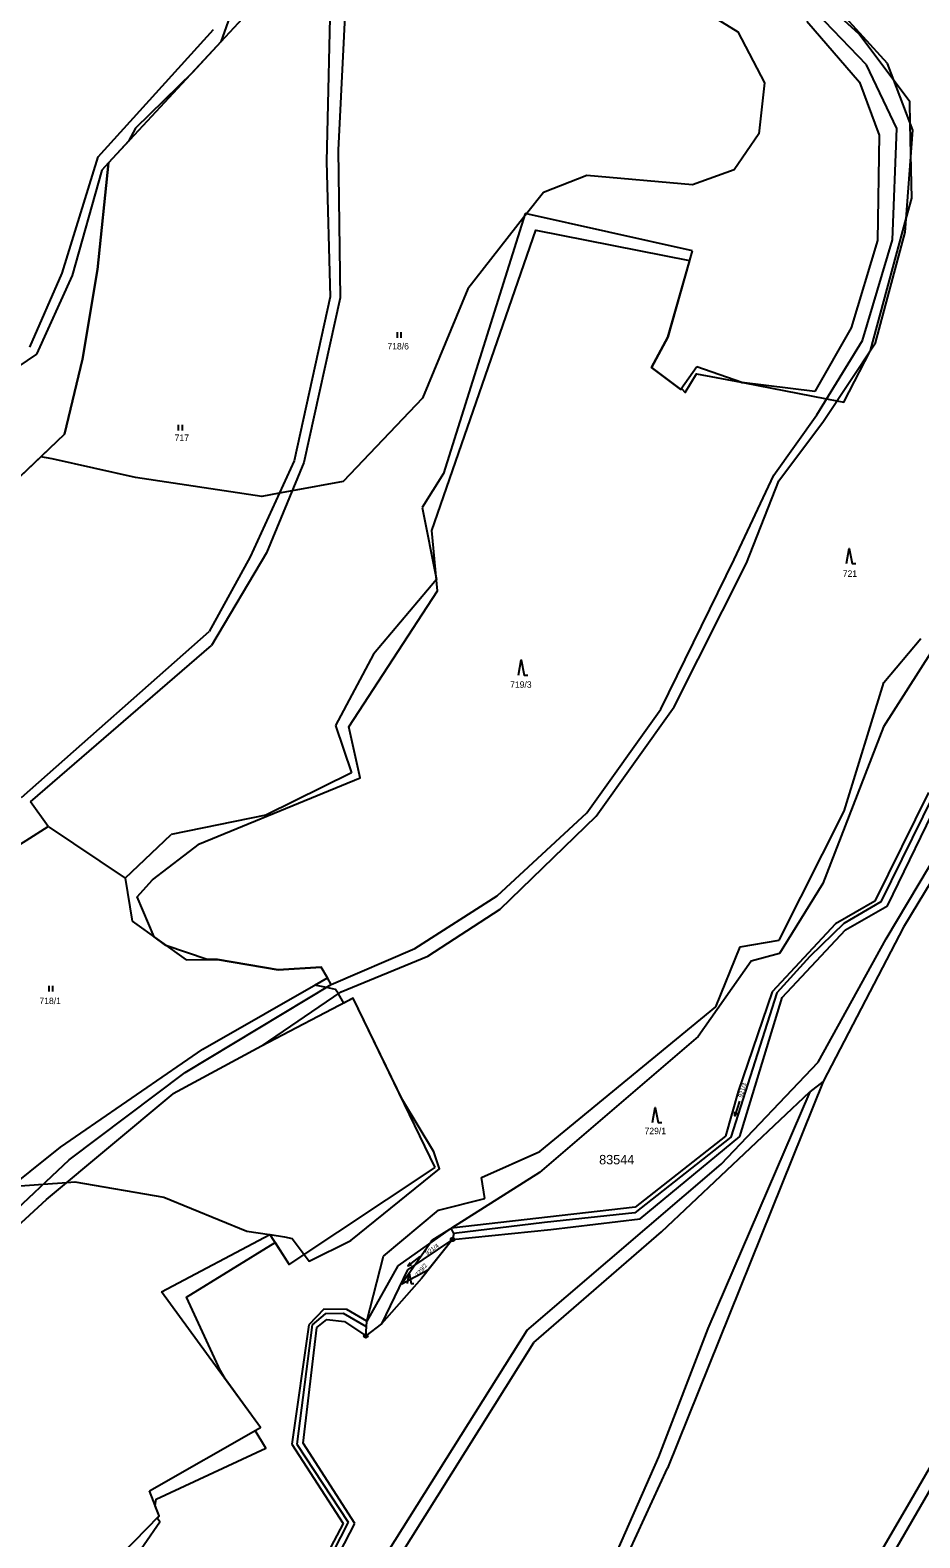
# Model space of a CAD drawing. Extents: x -547623 to -538651, y -1096714 to -1086522.
# Drawn here: x -544362.8 to -544127.4, y -1093972.7 to -1093573.6 of the extents above; entities that cross this region are included whole.
import ezdxf

# ---------------------------------------------------------------- set-up
doc = ezdxf.new("R2010")
doc.units = 0
for name, color, linetype in [('Vrstva 1', 7, 'Continuous'), ('Vrstva 25', 7, 'Continuous'), ('Vrstva 41', 7, 'Continuous'), ('Vrstva 52', 7, 'Continuous'), ('Vrstva 53', 7, 'Continuous'), ('Vrstva 83', 7, 'Continuous'), ('Vrstva 86', 7, 'Continuous')]:
    doc.layers.add(name, color=color, linetype=linetype)

msp = doc.modelspace()

# ---------------------------------------------------------------- linework, layer by layer
at = {"layer": 'Vrstva 1'}
for points in [[(-544141.5, -1093582.7), (-544165.76, -1093557.36)], [(-544283.31, -1093558.84), (-544284.44, -1093608.36)], [(-544279.15, -1093560.88), (-544281.34, -1093605.3)], [(-544342.12, -1093608.69), (-544305.41, -1093569.13)], [(-544135.89, -1093582.35), (-544148.81, -1093568.22)], [(-544344.88, -1093607.09), (-544314.3, -1093573.38)], [(-544157.24, -1093571.16), (-544143.3, -1093587.3)], [(-544129.25, -1093600.01), (-544135.89, -1093582.35)], [(-544133.47, -1093599.59), (-544141.5, -1093582.7)], [(-544143.3, -1093587.3), (-544138.16, -1093601.33)], [(-544138.16, -1093601.33), (-544138.53, -1093629.26)], [(-544134.56, -1093629.07), (-544133.47, -1093599.59)], [(-544131.24, -1093627.07), (-544129.25, -1093600.01)], [(-544281.34, -1093605.3), (-544280.82, -1093644.45)], [(-544354.36, -1093637.91), (-544344.88, -1093607.09)], [(-544345.05, -1093636.88), (-544342.12, -1093608.69)], [(-544342.12, -1093608.69), (-544343.89, -1093610.63)], [(-544284.44, -1093608.36), (-544283.42, -1093644.15)], [(-544343.89, -1093610.63), (-544351.69, -1093638.52)], [(-544231.86, -1093622.13), (-544253.47, -1093690.89)], [(-544187.58, -1093631.95), (-544231.86, -1093622.13)], [(-544138.53, -1093629.26), (-544145.5, -1093652.33)], [(-544142.53, -1093655.71), (-544134.56, -1093629.07)], [(-544139.11, -1093656.3), (-544131.24, -1093627.07)], [(-544194.09, -1093654.8), (-544187.58, -1093631.95)], [(-544362.97, -1093657.45), (-544354.36, -1093637.91)], [(-544351.69, -1093638.52), (-544361.15, -1093659.37)], [(-544349.04, -1093660.69), (-544345.05, -1093636.88)], [(-544283.42, -1093644.15), (-544292.98, -1093687.56)], [(-544280.82, -1093644.45), (-544290.41, -1093688.03)], [(-544145.5, -1093652.33), (-544155.19, -1093669.26)], [(-544198.37, -1093662.83), (-544194.09, -1093654.8)], [(-544154.63, -1093675.36), (-544142.53, -1093655.71)], [(-544152.89, -1093677.05), (-544139.11, -1093656.3)], [(-544361.15, -1093659.37), (-544377.72, -1093670.57)], [(-544353.73, -1093680.49), (-544349.04, -1093660.69)], [(-544190.67, -1093668.66), (-544198.37, -1093662.83)], [(-544186.41, -1093662.65), (-544190.67, -1093668.66)], [(-544174.49, -1093666.83), (-544186.41, -1093662.65)], [(-544155.19, -1093669.26), (-544174.49, -1093666.83)], [(-544166.02, -1093691.38), (-544154.63, -1093675.36)], [(-544164.71, -1093692.89), (-544152.89, -1093677.05)], [(-544373.17, -1093698.99), (-544353.73, -1093680.49)], [(-544292.98, -1093687.56), (-544304.58, -1093712.95)], [(-544290.41, -1093688.03), (-544300.33, -1093711.96)], [(-544253.47, -1093690.89), (-544259.1, -1093699.96)], [(-544176.52, -1093713.7), (-544166.02, -1093691.38)], [(-544173.22, -1093714.7), (-544164.71, -1093692.89)], [(-544259.1, -1093699.96), (-544255.29, -1093719.03)], [(-544304.58, -1093712.95), (-544315.47, -1093732.72)], [(-544300.33, -1093711.96), (-544314.83, -1093736.49)], [(-544195.95, -1093753.28), (-544176.52, -1093713.7)], [(-544192.41, -1093752.68), (-544173.22, -1093714.7)], [(-544255.29, -1093719.03), (-544271.97, -1093738.72)], [(-544365.17, -1093776.69), (-544315.47, -1093732.72)], [(-544362.73, -1093777.86), (-544314.83, -1093736.49)], [(-544136.87, -1093746.24), (-544127.14, -1093734.57)], [(-544271.97, -1093738.72), (-544282.06, -1093757.6)], [(-544147.37, -1093780.34), (-544136.87, -1093746.24)], [(-544215.48, -1093780.72), (-544195.95, -1093753.28)], [(-544213.06, -1093781.67), (-544192.41, -1093752.68)], [(-544096.01, -1093752.19), (-544131.68, -1093811.05)], [(-544282.06, -1093757.6), (-544277.77, -1093770.15)], [(-544277.77, -1093770.15), (-544300.51, -1093781.38)], [(-544358.11, -1093784.34), (-544362.73, -1093777.86)], [(-544125.06, -1093775.35), (-544139.27, -1093804.11)], [(-544135.92, -1093805.37), (-544121.21, -1093775.05)], [(-544300.51, -1093781.38), (-544325.53, -1093786.51)], [(-544239.28, -1093802.74), (-544215.48, -1093780.72)], [(-544238.42, -1093806.24), (-544213.06, -1093781.67)], [(-544164.59, -1093814.46), (-544147.37, -1093780.34)], [(-544136.31, -1093814.14), (-544116.37, -1093780.69)], [(-544397.19, -1093809.18), (-544358.11, -1093784.34)], [(-544358.11, -1093784.34), (-544337.71, -1093798.08)], [(-544337.71, -1093798.08), (-544325.53, -1093786.51)], [(-544337.71, -1093798.08), (-544335.89, -1093809.47)], [(-544261, -1093816.64), (-544239.28, -1093802.74)], [(-544139.27, -1093804.11), (-544149.67, -1093810.15)], [(-544147.08, -1093811.76), (-544135.92, -1093805.37)], [(-544335.89, -1093809.47), (-544321.59, -1093819.68)], [(-544257.58, -1093818.7), (-544238.42, -1093806.24)], [(-544149.67, -1093810.15), (-544166.48, -1093828.17)], [(-544163.84, -1093829.61), (-544147.08, -1093811.76)], [(-544154.25, -1093846.76), (-544136.31, -1093814.14)], [(-544131.68, -1093811.05), (-544152.92, -1093851.86)], [(-544283.19, -1093826.23), (-544261, -1093816.64)], [(-544181.34, -1093832.12), (-544174.95, -1093816.27)], [(-544174.95, -1093816.27), (-544164.59, -1093814.46)], [(-544321.59, -1093819.68), (-544313.28, -1093819.6)], [(-544313.28, -1093819.6), (-544297.25, -1093822.37)], [(-544297.25, -1093822.37), (-544285.85, -1093821.61)], [(-544284.19, -1093824.46), (-544285.85, -1093821.61)], [(-544280.55, -1093828.19), (-544257.58, -1093818.7)], [(-544317.12, -1093843.32), (-544284.19, -1093824.46)], [(-544283.19, -1093826.23), (-544284.19, -1093824.46)], [(-544321.81, -1093849.54), (-544283.19, -1093826.23)], [(-544301.62, -1093842.5), (-544280.55, -1093828.19)], [(-544277.34, -1093829.83), (-544301.62, -1093842.5)], [(-544255.62, -1093874.7), (-544277.34, -1093829.83)], [(-544166.48, -1093828.17), (-544175.45, -1093854.57)], [(-544175, -1093866.49), (-544163.84, -1093829.61)], [(-544227.91, -1093870.45), (-544181.34, -1093832.12)], [(-544354.81, -1093869.25), (-544317.12, -1093843.32)], [(-544301.62, -1093842.5), (-544325.04, -1093855.17)], [(-544352.52, -1093872.65), (-544321.81, -1093849.54)], [(-544179.98, -1093873.82), (-544154.25, -1093846.76)], [(-544152.92, -1093851.86), (-544194.16, -1093954.3)], [(-544152.92, -1093851.86), (-544156.46, -1093854.59)], [(-544358.53, -1093883.13), (-544325.04, -1093855.17)], [(-544195.78, -1093891.69), (-544156.46, -1093854.59)], [(-544156.46, -1093854.59), (-544183.51, -1093917.25)], [(-544175.45, -1093854.57), (-544178.77, -1093866.4)], [(-544387.06, -1093895.07), (-544354.81, -1093869.25)], [(-544178.77, -1093866.4), (-544202.71, -1093885.17)], [(-544201.42, -1093888.29), (-544175, -1093866.49)], [(-544403.16, -1093920.26), (-544352.52, -1093872.65)], [(-544243.42, -1093877.28), (-544227.91, -1093870.45)], [(-544199.51, -1093890.51), (-544179.98, -1093873.82)], [(-544294.33, -1093900.31), (-544255.62, -1093874.7)], [(-544242.53, -1093882.86), (-544243.42, -1093877.28)], [(-544400.78, -1093921.99), (-544358.53, -1093883.13)], [(-544269.29, -1093898.12), (-544254.78, -1093885.96)], [(-544254.78, -1093885.96), (-544242.53, -1093882.86)], [(-544202.71, -1093885.17), (-544251.38, -1093890.73)], [(-544225.05, -1093891.11), (-544201.42, -1093888.29)], [(-544328.06, -1093907.6), (-544299.39, -1093892.36)], [(-544299.39, -1093892.36), (-544294.33, -1093900.31)], [(-544251.38, -1093890.73), (-544265.53, -1093900.71)], [(-544251.02, -1093893.7), (-544263, -1093901.78)], [(-544250.68, -1093892.15), (-544251.38, -1093890.73)], [(-544251.02, -1093893.7), (-544225.05, -1093891.11)], [(-544231.42, -1093917.78), (-544199.51, -1093890.51)], [(-544229.5, -1093920.98), (-544195.78, -1093891.69)], [(-544273.74, -1093915.31), (-544269.29, -1093898.12)], [(-544265.53, -1093900.71), (-544273.74, -1093915.31)], [(-544263, -1093901.78), (-544269.87, -1093916.09)], [(-544301.89, -1093943.46), (-544328.06, -1093907.6)], [(-544285.1, -1093912.17), (-544289.1, -1093916.33)], [(-544279.03, -1093912.25), (-544285.1, -1093912.17)], [(-544273.74, -1093915.31), (-544279.03, -1093912.25)], [(-544289.1, -1093916.33), (-544293.56, -1093947.89)], [(-544290.56, -1093947.68), (-544286.96, -1093917)], [(-544286.96, -1093917), (-544284.33, -1093914.88)], [(-544284.33, -1093914.88), (-544279.68, -1093915.4)], [(-544279.68, -1093915.4), (-544274.01, -1093919.25)], [(-544273.83, -1093916.82), (-544273.74, -1093915.31)], [(-544231.42, -1093917.78), (-544268.23, -1093976.49)], [(-544183.51, -1093917.25), (-544196.54, -1093951.3)], [(-544265.71, -1093978.73), (-544229.5, -1093920.98)], [(-544102, -1093920.7), (-544141.53, -1093989.17)], [(-544331.28, -1093960.3), (-544301.89, -1093943.46)], [(-544293.56, -1093947.89), (-544280.03, -1093968.88)], [(-544276.92, -1093968.88), (-544290.56, -1093947.68)], [(-544196.54, -1093951.3), (-544221.1, -1094006.97)], [(-544218.52, -1094007.2), (-544194.16, -1093954.3)], [(-544328.67, -1093966.87), (-544331.28, -1093960.3)], [(-544355.24, -1093994.15), (-544328.67, -1093966.87)], [(-544280.03, -1093968.88), (-544285.81, -1093979.92)], [(-544283.7, -1093982.03), (-544276.92, -1093968.88)]]:
    msp.add_lwpolyline(points, dxfattribs=at)
at = {"layer": 'Vrstva 25'}
for p, q in [((-544265.62, -1093655.01), (-544265.62, -1093653.51)), ((-544264.62, -1093655.01), (-544264.62, -1093653.51)), ((-544323.55, -1093679.51), (-544323.55, -1093678.01)), ((-544322.55, -1093679.51), (-544322.55, -1093678.01)), ((-544357.86, -1093828.08), (-544357.86, -1093826.58)), ((-544356.86, -1093828.08), (-544356.86, -1093826.58))]:
    msp.add_line(p, q, dxfattribs=at)
for points in [[(-544146.81, -1093714.77), (-544146.11, -1093710.77), (-544145.31, -1093714.77), (-544144.31, -1093714.77)], [(-544233.58, -1093744.28), (-544232.88, -1093740.28), (-544232.08, -1093744.28), (-544231.08, -1093744.28)], [(-544175.11, -1093857.14), (-544176.33, -1093860.98), (-544175.7, -1093860.12)], [(-544198.13, -1093862.76), (-544197.43, -1093858.76), (-544196.63, -1093862.76), (-544195.63, -1093862.76)], [(-544176.33, -1093860.98), (-544176.34, -1093859.92)], [(-544259.71, -1093898.26), (-544262.91, -1093900.7), (-544261.91, -1093900.35)], [(-544262.91, -1093900.7), (-544262.31, -1093899.82)], [(-544262.99, -1093905.34), (-544262.52, -1093902.66), (-544261.98, -1093905.34), (-544261.31, -1093905.34)]]:
    msp.add_lwpolyline(points, dxfattribs=at)
at = {"layer": 'Vrstva 41'}
for points in [[(-544123.85, -1093776.18), (-544137.68, -1093804.35)], [(-544123.85, -1093776.18), (-544137.68, -1093804.35)], [(-544137.68, -1093804.35), (-544147.48, -1093810.02)], [(-544137.68, -1093804.35), (-544147.48, -1093810.02)], [(-544147.48, -1093810.02), (-544156.45, -1093818.84)], [(-544147.48, -1093810.02), (-544156.45, -1093818.84)], [(-544156.45, -1093818.84), (-544165.26, -1093828.42)], [(-544156.45, -1093818.84), (-544165.26, -1093828.42)], [(-544165.26, -1093828.42), (-544177.36, -1093866.67)], [(-544165.26, -1093828.42), (-544177.36, -1093866.67)], [(-544177.36, -1093866.67), (-544202.78, -1093886.65)], [(-544177.36, -1093866.67), (-544202.78, -1093886.65)], [(-544226.67, -1093889.25), (-544250.68, -1093892.15)], [(-544226.67, -1093889.25), (-544250.68, -1093892.15)], [(-544202.78, -1093886.65), (-544226.67, -1093889.25)], [(-544202.78, -1093886.65), (-544226.67, -1093889.25)], [(-544251.02, -1093893.7), (-544259.26, -1093904.01)], [(-544251.02, -1093893.7), (-544259.26, -1093904.01)], [(-544250.68, -1093892.15), (-544251.02, -1093893.7)], [(-544250.68, -1093892.15), (-544251.02, -1093893.7)], [(-544259.26, -1093904.01), (-544269.87, -1093916.09)], [(-544259.26, -1093904.01), (-544269.87, -1093916.09)], [(-544098.58, -1093908.92), (-544129.74, -1093962.73)], [(-544098.58, -1093908.92), (-544129.74, -1093962.73)], [(-544284.77, -1093913.36), (-544288.2, -1093916.31)], [(-544284.77, -1093913.36), (-544288.2, -1093916.31)], [(-544279.95, -1093913.28), (-544284.77, -1093913.36)], [(-544279.95, -1093913.28), (-544284.77, -1093913.36)], [(-544273.83, -1093916.82), (-544279.95, -1093913.28)], [(-544273.83, -1093916.82), (-544279.95, -1093913.28)], [(-544288.2, -1093916.31), (-544292.28, -1093947.9)], [(-544288.2, -1093916.31), (-544292.28, -1093947.9)], [(-544269.87, -1093916.09), (-544274.01, -1093919.25)], [(-544269.87, -1093916.09), (-544274.01, -1093919.25)], [(-544274.01, -1093919.25), (-544273.83, -1093916.82)], [(-544274.01, -1093919.25), (-544273.83, -1093916.82)], [(-544292.28, -1093947.9), (-544278.65, -1093968.55)], [(-544292.28, -1093947.9), (-544278.65, -1093968.55)], [(-544129.74, -1093962.73), (-544145.32, -1093989.4)], [(-544129.74, -1093962.73), (-544145.32, -1093989.4)], [(-544278.65, -1093968.55), (-544284.88, -1093980.64)], [(-544278.65, -1093968.55), (-544284.88, -1093980.64)]]:
    msp.add_lwpolyline(points, dxfattribs=at)
at = {"layer": 'Vrstva 52'}
for points in [[(-544315.02, -1093518.45), (-544313.07, -1093532.25), (-544312.07, -1093533.51), (-544309.06, -1093537.66), (-544307.5, -1093545.43), (-544307.5, -1093563.41), (-544309.52, -1093568.66), (-544312.37, -1093576.64), (-544319.88, -1093584.73), (-544335, -1093599.5), (-544336.81, -1093602.97), (-544342.12, -1093608.69), (-544345.05, -1093636.88), (-544349.04, -1093660.69), (-544353.73, -1093680.49), (-544360.06, -1093686.51)], [(-544290.36, -1093897.68), (-544289, -1093899.5), (-544278, -1093894), (-544254.5, -1093875), (-544256, -1093870.5), (-544264.29, -1093856.79), (-544277.34, -1093829.83), (-544279.81, -1093831.12), (-544281.28, -1093828.69), (-544282, -1093827.5), (-544284.44, -1093826.99), (-544287.48, -1093826.35), (-544284.19, -1093824.46), (-544285.85, -1093821.61), (-544297.25, -1093822.37), (-544313.28, -1093819.6), (-544315.98, -1093819.63), (-544326.9, -1093815.89), (-544330.07, -1093813.62), (-544334.5, -1093803), (-544330.5, -1093798.5), (-544318, -1093789), (-544275.5, -1093771.5), (-544278.5, -1093758), (-544255, -1093722), (-544256.5, -1093706), (-544229, -1093626.5), (-544188.32, -1093634.55), (-544194.09, -1093654.8), (-544198.37, -1093662.83), (-544190.67, -1093668.66), (-544190.49, -1093668.4), (-544189.5, -1093669.5), (-544186.5, -1093664.5), (-544174.62, -1093666.78), (-544174.49, -1093666.83), (-544174.18, -1093666.87), (-544152.03, -1093671.13), (-544149.31, -1093671.65), (-544147.5, -1093672), (-544140.5, -1093658.5), (-544140.45, -1093658.32), (-544130.97, -1093623.42), (-544129.5, -1093618), (-544129.73, -1093606.48), (-544129.89, -1093598.32), (-544130, -1093592.5), (-544134.16, -1093586.96), (-544143.5, -1093574.5), (-544171.5, -1093549)], [(-544209.5, -1093553), (-544175.5, -1093574), (-544168.5, -1093587.5), (-544170, -1093601), (-544176.5, -1093610.5), (-544187.5, -1093614.5), (-544215.5, -1093612), (-544227, -1093616.5), (-544231.48, -1093622.21), (-544232.16, -1093623.08), (-544247, -1093642), (-544259, -1093671), (-544280, -1093693), (-544293.51, -1093695.51), (-544296.9, -1093696.14), (-544301.5, -1093697), (-544335, -1093692), (-544357, -1093687), (-544360.06, -1093686.51)], [(-544360.06, -1093686.51), (-544373.17, -1093698.99)], [(-544083.17, -1093734.21), (-544083.32, -1093737.82), (-544085.05, -1093737.6), (-544117.54, -1093758.21), (-544123.85, -1093776.18), (-544137.68, -1093804.35), (-544147.48, -1093810.02), (-544156.45, -1093818.84), (-544165.26, -1093828.42), (-544177.36, -1093866.67), (-544202.78, -1093886.65), (-544226.67, -1093889.25), (-544250.68, -1093892.15), (-544251.02, -1093893.7), (-544257.39, -1093901.67)], [(-544124.5, -1093738.5), (-544137, -1093758), (-544153, -1093799.5), (-544164.5, -1093818), (-544172, -1093820), (-544186, -1093840), (-544228, -1093876), (-544251.31, -1093890.72), (-544251.37, -1093890.76), (-544251.87, -1093891.08), (-544256.5, -1093894), (-544256.97, -1093894.67), (-544260.95, -1093900.4), (-544264.5, -1093905.5), (-544257.39, -1093901.67)], [(-544503.5, -1094000), (-544499.5, -1093960.5), (-544487, -1093935.5), (-544467, -1093912), (-544438.5, -1093891), (-544408, -1093882.5), (-544392.56, -1093881.42), (-544389.4, -1093881.19), (-544367.84, -1093879.68), (-544359.37, -1093879.09), (-544353.17, -1093878.65), (-544351, -1093878.5), (-544327.5, -1093882.5), (-544305.5, -1093891.5), (-544299.47, -1093892.4), (-544299.35, -1093892.42), (-544295.5, -1093893), (-544293.5, -1093893.5)], [(-544293.5, -1093893.5), (-544290.36, -1093897.68)], [(-544341, -1093986.5), (-544328.5, -1093968.5), (-544329.26, -1093967.48), (-544328.67, -1093966.87), (-544329.72, -1093964.23), (-544329.5, -1093962.5), (-544300.5, -1093949), (-544303.28, -1093944.26), (-544301.89, -1093943.46), (-544311.25, -1093930.63), (-544312.5, -1093928.5), (-544321.5, -1093909), (-544298, -1093894.54), (-544294.33, -1093900.31), (-544290.36, -1093897.68)]]:
    msp.add_lwpolyline(points, dxfattribs=at)
at = {"layer": 'Vrstva 83'}
for centre, radius in [((-544251.02, -1093893.7), 0.5), ((-544251.02, -1093893.7), 0.1), ((-544274.01, -1093919.25), 0.5), ((-544274.01, -1093919.25), 0.1)]:
    msp.add_circle(centre, radius, dxfattribs=at)

# ---------------------------------------------------------------- texts
at = {"layer": 'Vrstva 53'}
msp.add_text('83544', height=2.5, dxfattribs=at).set_placement((-544212.25, -1093873.83))
at = {"layer": 'Vrstva 86'}
for s, p in [('718/6', (-544268.29, -1093658.09)), ('717', (-544324.6, -1093682.3)), ('721', (-544147.76, -1093718.29)), ('719/3', (-544235.81, -1093747.66)), ('718/1', (-544360.4, -1093831.4)), ('729/1', (-544200.23, -1093865.84))]:
    msp.add_text(s, height=1.7, dxfattribs=at).set_placement(p)
for s, rotation, p in [('921/3', 72.7655, (-544174.39, -1093856.22)), ('921/4', 35.3657, (-544257.77, -1093897.91)), ('729/2', 51.4054, (-544260.13, -1093903.68))]:
    msp.add_text(s, height=1.14, rotation=rotation, dxfattribs=at).set_placement(p)

doc.saveas('drawing.dxf')
